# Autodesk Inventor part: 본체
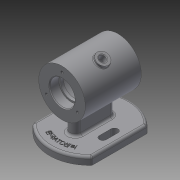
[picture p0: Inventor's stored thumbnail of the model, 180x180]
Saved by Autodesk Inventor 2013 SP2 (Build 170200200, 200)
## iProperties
Created: 2022-02
Part Number: 본체
Material: Generic
Document SubType Name: Modeling
Designer: a
Density: 1 g/cm^3
Mass: 183.432 g
Surface Area: 489.776 cm^2
Volume: 183.432 cm^3
Author: a
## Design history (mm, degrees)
sketch "스케치1"
  geometry: L1 (-36, 0)-(36, 0); L2 (-36, 0)-(-36, 30); L3 (-36, 30)-(36, 30); L4 (36, 30)-(36, 0); L5 (-24, 16)-(-24, 14); L6 (-24, 14)-(-20, 14); L7 (-20, 14)-(-20, 25); L8 (-20, 25)-(20, 25); L9 (20, 25)-(20, 14); L10 (20, 14)-(24, 14); L11 (24, 14)-(24, 16); L12 (24, 16)-(36, 16); L13 (-24, 16)-(-36, 16); 2 further points
  constraints: 26 end point, 4 parallel, 3 perpendicular, 2 point on line, 1 coincident, 1 collinear, 1 horizontal, 1 midpoint, 1 vertical
  dimensions: "d0" = 72 distance of L1.start L1.end; "d1" = 60 diameter of L3 L1; "d2" = 50 diameter of L8 L1; "d3" = 32 diameter of L12 L1; "d4" = 28 diameter of L10 L1; "d5" = 28 diameter of L6 L1; "d6" = 32 diameter of L13 L1; "d7" = 12 distance of L5.start L13.end; "d8" = 40 distance of L8.end L7.end; "d9" = 4 distance of L6.end L5.end; "d10" = 4 distance of L10.end L9.end
revolve "회전1" sketch "스케치1" stored, may be unused: angle "d11" = 90 deg
node "작업 평면1"
sketch "스케치2"
  geometry: L1 (-35.496, 38)-(35.496, 38); L2 (35.496, 38)-(35.496, -38); L3 (35.496, -38)-(-35.496, -38); L4 (-35.496, -38)-(-35.496, 38); L5 (-35.496, 38)-(35.496, -38); L6 (35.496, 38)-(-35.496, -38); A1 r 52 centre (0, 0) between (-35.496, 38) and (-35.496, -38); A2 r 52 centre (0, 0) between (35.496, -38) and (35.496, 38); 1 further point
  constraints: 12 end point, 4 point on circle, 2 centre point, 2 midpoint, 2 parallel, 1 coincident, 1 horizontal, 1 perpendicular
  dimensions: "d14" = 76 distance of L1.end L2.end; "d15" = 52 radius of A1
extrude "돌출1" join sketch "스케치2" distance "d16" = 10; taper "d17" = 0 deg
sketch "스케치3"
  geometry: L1 (-19, 7)-(19, 7); L2 (19, 7)-(19, -7); L3 (19, -7)-(-19, -7); L4 (-19, -7)-(-19, 7); L5 (-19, 7)-(19, -7); L6 (19, 7)-(-19, -7); L7 (-7.5, 28.5)-(7.5, 28.5); L8 (7.5, 28.5)-(7.5, 19.5); L9 (7.5, 19.5)-(-7.5, 19.5); L10 (-7.5, 19.5)-(-7.5, 28.5); L11 (-7.5, 28.5)-(7.5, 19.5); L12 (7.5, 28.5)-(-7.5, 19.5); L13 (-7.5, -19.5)-(7.5, -19.5); L14 (7.5, -19.5)-(7.5, -28.5); L15 (7.5, -28.5)-(-7.5, -28.5); L16 (-7.5, -28.5)-(-7.5, -19.5); L17 (-7.5, -19.5)-(7.5, -28.5); L18 (7.5, -19.5)-(-7.5, -28.5); A1 r 52 centre (0, 0) between (35.496, -38) and (35.496, 38) reference; A2 r 52 centre (0, 0) between (-35.496, 38) and (-35.496, -38) reference; 12 further points
  constraints: 36 end point, 16 midpoint, 8 vertical alignment, 6 parallel, 3 horizontal, 3 perpendicular, 12 other
  dimensions: "d18" = 38 distance of L2.end L3.end; "d19" = 14 distance of L1.end L2.end; "d20" = 15 distance of L8.end L9.end; "d21" = 9 distance of L7.end L8.end; "d22" = 15 distance of L14.end L15.end; "d23" = 9 distance of L13.end L14.end; "d24" = 24 distance of point (0, 24) A2.centre; "d25" = 24 distance of point (0, -24) A1.centre
extrude "돌출2" cut sketch "스케치3" distance "d26" = 10; taper "d27" = 0 deg
extrude "돌출3" join sketch "스케치3" stored distance "d28" = 10; taper "d29" = 0 deg
sketch "스케치4" dims "d30" = 46
  geometry: C1 r 16 at (0, 0) reference; 2 further points
  constraints: 2 vertical alignment, 1 coincident, 2 other
hole "구멍1" sketch "스케치4" at (0, 23) diameter "d31" = 3.242; stored, may be unused: countersink angle "d35" = 82 deg, drill point angle "d37" = 118 deg; dims "d32" = 8, "d33" = 3.023, "d34" = 2, "d36" = 10
sketch "스케치5"
  geometry: L1 (0, 0)-(30, 0); L2 (0, 0)-(28.579, 16.5); 1 further point
  constraints: 4 end point, 1 horizontal, 1 horizontal alignment, 1 other
  dimensions: "d41" = 33 distance of L1.start L2.end; "d42" = 30 deg angle of L1 L2
node "작업 평면2"
sketch "스케치6"
  geometry: C1 r 8 at (0, 0); 1 further point
  constraints: 1 centre point, 1 coincident
  dimensions: "d43" = 16 diameter of C1
extrude "돌출4" join sketch "스케치6" stored distance "d44" = 10; taper "d45" = 0 deg
sketch "스케치7"
  geometry: C1 r 8 at (0, 0) reference; C2 r 4 at (0, 0)
  constraints: 1 centre point, 1 coincident
  dimensions: "d46" = 8 diameter of C2
extrude "돌출5" cut sketch "스케치7" stored distance "d47" = 10; taper "d48" = 0 deg
sketch "스케치8"
  geometry: C1 r 42.5 at (0, 0); A1 r 52 centre (0, 0) between (35.496, -38) and (35.496, 38) reference
  constraints: 1 centre point, 1 coincident, 1 other
  dimensions: "d49" = 85 diameter of C1
feature "엠보싱1" sketch "스케치8" dims "d14" = 76, "d15" = 52, "d50" = 0.5, "d51" = 0
fillet "모깎기1" dims "d52" = 3
fillet "모깎기2" dims "d53" = 3
fillet "모깎기3" dims "d54" = 3
fillet "모깎기4" dims "d55" = 1
chamfer "모따기1" distance "d56" = 1; stored, may be unused: second distance "d57" = 2, angle "d58" = 45 deg
fillet "모깎기5" dims "d59" = 0.3
fillet "모깎기6" dims "d60" = 3
node "솔리드1"
pattern_circular "원형 패턴1" dims angle "d39" = 360 deg
mirror "대칭1"
other parameters: "d12" = -62, "d13" = 104
